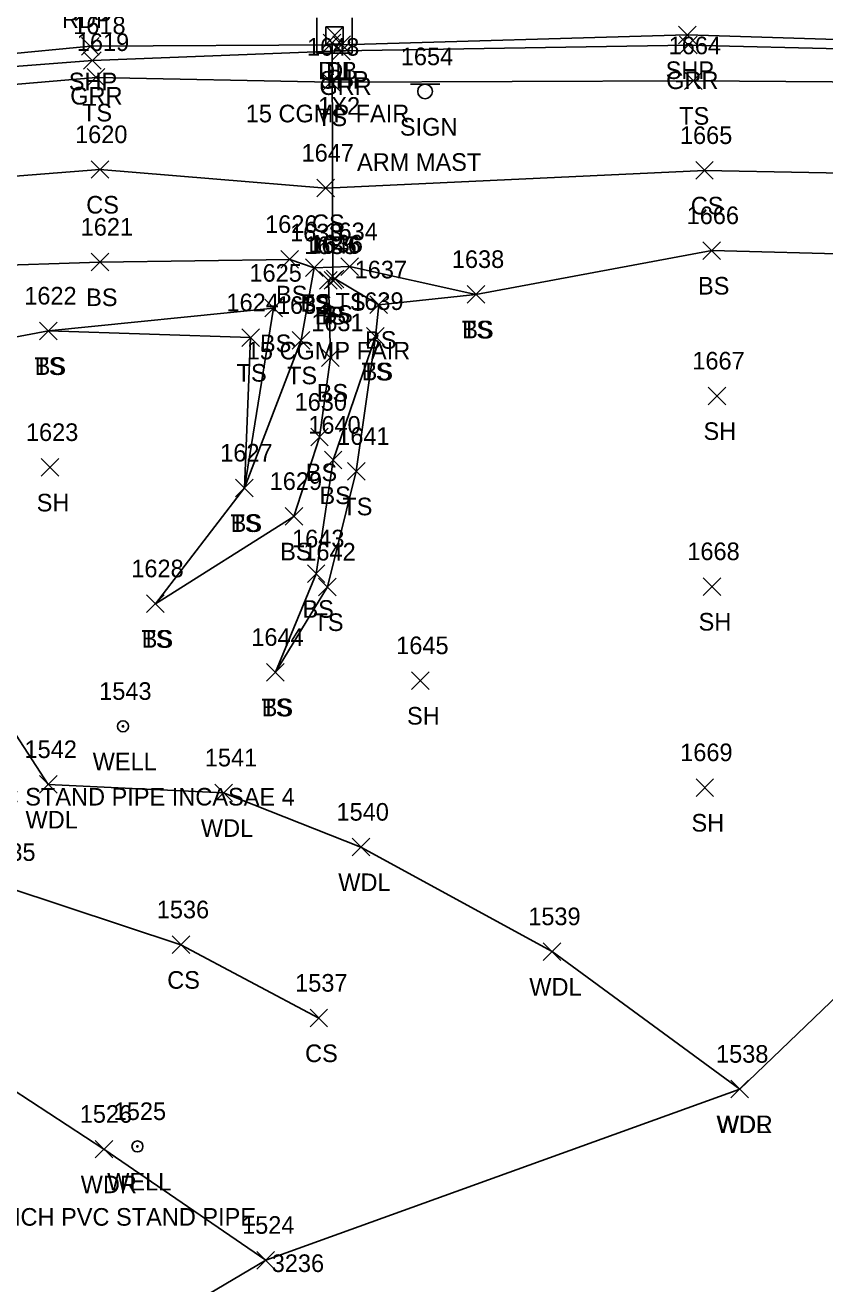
# Model space of a CAD drawing. Extents: x 49137 to 50946, y 9590 to 10709.
# Drawn here: x 50238.1 to 50328.9, y 9912 to 10054.9 of the extents above; entities that cross this region are included whole.
import ezdxf

# ---------------------------------------------------------------- set-up
doc = ezdxf.new("R2010")
doc.units = 0
for name, color, linetype in [('D_A', 7, 'Continuous'), ('D_C', 7, 'Continuous'), ('D_I', 7, 'Continuous'), ('D_TIC', 7, 'Continuous'), ('DCP', 7, 'Continuous'), ('DS', 7, 'Continuous'), ('L_A', 7, 'Continuous'), ('L_I', 7, 'Continuous'), ('L_TIC', 7, 'Continuous'), ('LAWA', 7, 'Continuous'), ('LELB', 7, 'Continuous'), ('LSOGP', 7, 'Continuous'), ('P_A', 7, 'Continuous'), ('P_TIC', 7, 'Continuous'), ('PSP', 7, 'Continuous'), ('R_A', 7, 'Continuous'), ('R_I', 7, 'Continuous'), ('R_TIC', 7, 'Continuous'), ('RGR', 7, 'Continuous'), ('S_A', 7, 'Continuous'), ('S_C', 7, 'Continuous'), ('S_I', 7, 'Continuous'), ('SSGN', 7, 'Continuous'), ('U_A', 7, 'Continuous'), ('U_C', 7, 'Continuous'), ('U_I', 7, 'Continuous'), ('UWW', 7, 'Continuous')]:
    doc.layers.add(name, color=color, linetype=linetype)

msp = doc.modelspace()

# ---------------------------------------------------------------- linework, layer by layer
at = {"layer": 'D_TIC'}
for points in [[(50271.92, 10051.89), (50273.92, 10053.89)], [(50273.92, 10051.89), (50271.92, 10053.89)], [(50272.23, 10052.76), (50274.23, 10054.76)], [(50274.23, 10052.76), (50272.23, 10054.76)], [(50272.02, 10024.96), (50274.02, 10026.96)], [(50274.02, 10024.96), (50272.02, 10026.96)]]:
    msp.add_lwpolyline(points, dxfattribs=at)
at = {"layer": 'DCP'}
msp.add_lwpolyline([(50273.02, 10025.96), (50272.92, 10052.89)], dxfattribs=at)
at = {"layer": 'DS'}
for p, q in [((50271.19, 10051.75), (50271.19, 10055.75)), ((50275.19, 10055.75), (50275.19, 10051.75)), ((50272.19, 10052.75), (50272.19, 10054.75)), ((50272.19, 10054.75), (50274.19, 10054.75)), ((50273.2, 10053.75), (50273.2, 10053.75)), ((50273.2, 10053.75), (50273.2, 10053.75)), ((50274.19, 10054.75), (50274.19, 10052.75)), ((50274.19, 10052.75), (50272.19, 10052.75)), ((50275.19, 10051.75), (50271.19, 10051.75))]:
    msp.add_line(p, q, dxfattribs=at)
at = {"layer": 'L_TIC'}
for points in [[(50245.1, 10047.99), (50247.1, 10049.99)], [(50247.1, 10047.99), (50245.1, 10049.99)], [(50271.8, 10047.46), (50273.8, 10049.46)], [(50273.8, 10047.46), (50271.8, 10049.46)], [(50312.94, 10047.62), (50314.94, 10049.62)], [(50314.94, 10047.62), (50312.94, 10049.62)], [(50245.55, 10037.53), (50247.55, 10039.53)], [(50247.55, 10037.53), (50245.55, 10039.53)], [(50314.22, 10037.43), (50316.22, 10039.43)], [(50316.22, 10037.43), (50314.22, 10039.43)], [(50271.19, 10035.43), (50273.19, 10037.43)], [(50273.19, 10035.43), (50271.19, 10037.43)], [(50267.1, 10027.33), (50269.1, 10029.33)], [(50269.1, 10027.33), (50267.1, 10029.33)], [(50315.04, 10028.33), (50317.04, 10030.33)], [(50317.04, 10028.33), (50315.04, 10030.33)], [(50245.54, 10027.02), (50247.54, 10029.02)], [(50247.54, 10027.02), (50245.54, 10029.02)], [(50269.89, 10026.37), (50271.89, 10028.37)], [(50271.89, 10026.37), (50269.89, 10028.37)], [(50269.89, 10026.37), (50271.89, 10028.37)], [(50271.89, 10026.37), (50269.89, 10028.37)], [(50273.9, 10026.5), (50275.9, 10028.5)], [(50275.9, 10026.5), (50273.9, 10028.5)], [(50271.5, 10024.93), (50273.5, 10026.93)], [(50273.5, 10024.93), (50271.5, 10026.93)], [(50272.27, 10025.11), (50274.27, 10027.11)], [(50274.27, 10025.11), (50272.27, 10027.11)], [(50288.26, 10023.35), (50290.26, 10025.35)], [(50290.26, 10023.35), (50288.26, 10025.35)], [(50288.26, 10023.35), (50290.26, 10025.35)], [(50290.26, 10023.35), (50288.26, 10025.35)], [(50265.27, 10021.79), (50267.27, 10023.79)], [(50267.27, 10021.79), (50265.27, 10023.79)], [(50277.22, 10022.17), (50279.22, 10024.17)], [(50279.22, 10022.17), (50277.22, 10024.17)], [(50277.22, 10022.17), (50279.22, 10024.17)], [(50279.22, 10022.17), (50277.22, 10024.17)], [(50239.69, 10019.2), (50241.69, 10021.2)], [(50241.69, 10019.2), (50239.69, 10021.2)], [(50239.69, 10019.2), (50241.69, 10021.2)], [(50241.69, 10019.2), (50239.69, 10021.2)], [(50276.83, 10018.58), (50278.83, 10020.58)], [(50278.83, 10018.58), (50276.83, 10020.58)], [(50276.83, 10018.58), (50278.83, 10020.58)], [(50278.83, 10018.58), (50276.83, 10020.58)], [(50262.66, 10018.44), (50264.66, 10020.44)], [(50264.66, 10018.44), (50262.66, 10020.44)], [(50268.39, 10018.14), (50270.39, 10020.14)], [(50270.39, 10018.14), (50268.39, 10020.14)], [(50271.73, 10016.17), (50273.73, 10018.17)], [(50273.73, 10016.17), (50271.73, 10018.17)], [(50315.63, 10011.82), (50317.63, 10013.82)], [(50317.63, 10011.82), (50315.63, 10013.82)], [(50270.49, 10007.14), (50272.49, 10009.14)], [(50272.49, 10007.14), (50270.49, 10009.14)], [(50272.04, 10004.53), (50274.04, 10006.53)], [(50274.04, 10004.53), (50272.04, 10006.53)], [(50239.88, 10003.7), (50241.88, 10005.7)], [(50241.88, 10003.7), (50239.88, 10005.7)], [(50274.67, 10003.26), (50276.67, 10005.26)], [(50276.67, 10003.26), (50274.67, 10005.26)], [(50261.95, 10001.37), (50263.95, 10003.37)], [(50263.95, 10001.37), (50261.95, 10003.37)], [(50261.95, 10001.37), (50263.95, 10003.37)], [(50263.95, 10001.37), (50261.95, 10003.37)], [(50261.95, 10001.37), (50263.95, 10003.37)], [(50263.95, 10001.37), (50261.95, 10003.37)], [(50267.58, 9998.14), (50269.58, 10000.14)], [(50269.58, 9998.14), (50267.58, 10000.14)], [(50270.11, 9991.62), (50272.11, 9993.62)], [(50272.11, 9991.62), (50270.11, 9993.62)], [(50271.39, 9990.12), (50273.39, 9992.12)], [(50273.39, 9990.12), (50271.39, 9992.12)], [(50315.06, 9990.17), (50317.06, 9992.17)], [(50317.06, 9990.17), (50315.06, 9992.17)], [(50251.85, 9988.22), (50253.85, 9990.22)], [(50253.85, 9988.22), (50251.85, 9990.22)], [(50251.85, 9988.22), (50253.85, 9990.22)], [(50253.85, 9988.22), (50251.85, 9990.22)], [(50265.48, 9980.43), (50267.48, 9982.43)], [(50267.48, 9980.43), (50265.48, 9982.43)], [(50265.48, 9980.43), (50267.48, 9982.43)], [(50267.48, 9980.43), (50265.48, 9982.43)], [(50281.94, 9979.49), (50283.94, 9981.49)], [(50283.94, 9979.49), (50281.94, 9981.49)], [(50239.67, 9967.69), (50241.67, 9969.69)], [(50241.67, 9967.69), (50239.67, 9969.69)], [(50314.26, 9967.34), (50316.26, 9969.34)], [(50316.26, 9967.34), (50314.26, 9969.34)], [(50259.59, 9966.74), (50261.59, 9968.74)], [(50261.59, 9966.74), (50259.59, 9968.74)], [(50275.2, 9960.58), (50277.2, 9962.58)], [(50277.2, 9960.58), (50275.2, 9962.58)], [(50254.74, 9949.49), (50256.74, 9951.49)], [(50256.74, 9949.49), (50254.74, 9951.49)], [(50296.9, 9948.71), (50298.9, 9950.71)], [(50298.9, 9948.71), (50296.9, 9950.71)], [(50270.41, 9941.16), (50272.41, 9943.16)], [(50272.41, 9941.16), (50270.41, 9943.16)], [(50318.22, 9933.09), (50320.22, 9935.09)], [(50320.22, 9933.09), (50318.22, 9935.09)], [(50318.22, 9933.09), (50320.22, 9935.09)], [(50320.22, 9933.09), (50318.22, 9935.09)], [(50246, 9926.27), (50248, 9928.27)], [(50248, 9926.27), (50246, 9928.27)], [(50264.38, 9913.66), (50266.38, 9915.66)], [(50266.38, 9913.66), (50264.38, 9915.66)]]:
    msp.add_lwpolyline(points, dxfattribs=at)
at = {"layer": 'LAWA'}
for points in [[(50319.22, 9934.09), (50349.18, 9962.81), (50389.74, 9989.92), (50402.83, 10005.7), (50406.6, 10004.03), (50394.1, 9989.59), (50381.28, 9975.89)], [(50265.38, 9914.66), (50247, 9927.27), (50228.2, 9939.52), (50207.29, 9957.54), (50200.22, 9967.59), (50173.05, 9985.49), (50184.13, 9993.14), (50189.69, 9999.35)], [(50319.22, 9934.09), (50297.9, 9949.71), (50276.2, 9961.58), (50260.59, 9967.74), (50240.67, 9968.69), (50230.47, 9984.33), (50224.27, 9984.27), (50203.79, 9997.29), (50189.69, 9999.35)]]:
    msp.add_lwpolyline(points, dxfattribs=at)
at = {"layer": 'LELB'}
for points in [[(50167.44, 10041.81), (50201.55, 10044.88), (50212.32, 10046.12), (50246.1, 10048.99), (50272.8, 10048.46), (50313.94, 10048.62), (50350.81, 10048.34), (50387.74, 10046.03), (50413.04, 10045.35), (50435.45, 10042.61), (50477, 10035.72), (50497.96, 10034.79)], [(50107.47, 10020.38), (50144.2, 10028.78), (50165.65, 10031.22), (50202.05, 10039.61), (50215.24, 10036.08), (50246.55, 10038.53), (50272.19, 10036.43), (50315.22, 10038.43), (50350.77, 10037.74), (50388.31, 10038.81), (50412.12, 10038.05), (50434.22, 10033.95), (50476.27, 10030.6), (50502.33, 10026.06), (50519.95, 10026.12), (50528.33, 10023.44), (50558.5, 10017.09), (50596.1, 10007.75), (50623.13, 10001.96)], [(50278.22, 10023.17), (50289.26, 10024.35), (50316.04, 10029.33), (50350.22, 10028.42), (50386.55, 10029.79), (50399.58, 10030.09)], [(50218.69, 10027.11), (50246.54, 10028.02), (50268.1, 10028.33), (50270.89, 10027.37)], [(50240.69, 10020.2), (50263.66, 10019.44), (50262.95, 10002.37), (50269.39, 10019.14), (50270.89, 10027.37), (50274.9, 10027.5), (50289.26, 10024.35)], [(50252.85, 9989.22), (50268.58, 9999.14), (50271.49, 10008.14), (50272.73, 10017.17), (50272.5, 10025.93), (50273.27, 10026.11), (50278.22, 10023.17), (50277.83, 10019.58), (50273.04, 10005.53), (50271.11, 9992.62), (50266.48, 9981.43)], [(50221.39, 10016.59), (50240.69, 10020.2), (50266.27, 10022.79), (50262.95, 10002.37)], [(50277.83, 10019.58), (50275.67, 10004.26), (50272.39, 9991.12), (50266.48, 9981.43)], [(50262.95, 10002.37), (50252.85, 9989.22)], [(50200.22, 9967.59), (50202.79, 9981.16), (50217.66, 9971.94), (50235.97, 9957.01), (50255.74, 9950.49), (50271.41, 9942.16)]]:
    msp.add_lwpolyline(points, dxfattribs=at)
at = {"layer": 'LSOGP'}
msp.add_lwpolyline([(50172.36, 9837.78), (50185.48, 9838.52), (50189.39, 9851.5), (50202.19, 9864.77), (50219.85, 9877.61), (50226.92, 9887.06), (50233.45, 9889.4), (50242.1, 9900.88), (50265.38, 9914.66), (50319.22, 9934.09), (50349.18, 9962.81), (50381.27, 9975.89), (50394.04, 9971.93), (50398.71, 9968.32), (50400.43, 9966.52), (50406.78, 9963.51), (50419.71, 9962.53), (50427.02, 9958.62), (50466.07, 9973.83), (50480.4, 9980.25), (50492.08, 9978.32), (50501.38, 9976.22)], dxfattribs=at)
at = {"layer": 'P_TIC'}
for points in [[(50244.47, 10051.53), (50246.47, 10053.53)], [(50246.47, 10051.53), (50244.47, 10053.53)], [(50272.99, 10051.71), (50274.99, 10053.71)], [(50274.99, 10051.71), (50272.99, 10053.71)], [(50312.27, 10052.81), (50314.27, 10054.81)], [(50314.27, 10052.81), (50312.27, 10054.81)]]:
    msp.add_lwpolyline(points, dxfattribs=at)
at = {"layer": 'PSP'}
msp.add_lwpolyline([(49745.77, 9936.94), (49791.02, 9949.79), (49838.6, 9962.98), (49884.65, 9976.31), (49920.32, 9986.67), (49952.97, 9996.21), (49993.49, 10007.72), (50041.55, 10020.44), (50079.02, 10029.05), (50103.84, 10034.11), (50138.34, 10040.53), (50167.13, 10044.8), (50204.38, 10048.62), (50245.47, 10052.53), (50273.99, 10052.71), (50313.27, 10053.81), (50350.86, 10052.67), (50388.17, 10050.83), (50414.17, 10048.89), (50435.24, 10046.38), (50477.89, 10041.39), (50498.49, 10037.53)], dxfattribs=at)
at = {"layer": 'R_TIC'}
for points in [[(50312.38, 10051.67), (50314.38, 10053.67)], [(50314.38, 10051.67), (50312.38, 10053.67)], [(50272.98, 10051), (50274.98, 10053)], [(50274.98, 10051), (50272.98, 10053)], [(50244.69, 10049.91), (50246.69, 10051.91)], [(50246.69, 10049.91), (50244.69, 10051.91)]]:
    msp.add_lwpolyline(points, dxfattribs=at)
at = {"layer": 'RGR'}
msp.add_lwpolyline([(49745.96, 9935.74), (49791.34, 9948.66), (49838.49, 9962.28), (49885.39, 9975.73), (49920.7, 9985.37), (49953.18, 9995.29), (49993.74, 10006.79), (50040.75, 10019.43), (50079.3, 10027.88), (50102.09, 10032.68), (50138.52, 10039.64), (50167.15, 10043.61), (50204.31, 10047.75), (50245.69, 10050.91), (50273.98, 10052), (50313.38, 10052.67), (50351, 10051.76), (50388.09, 10049.85), (50414.02, 10047.85), (50436.27, 10045.35), (50477.66, 10040.11), (50498.48, 10036.57)], dxfattribs=at)
at = {"layer": 'SSGN'}
for p, q in [((50281.83, 10048.24), (50285.17, 10048.24)), ((50283.48, 10047.4), (50283.48, 10047.4))]:
    msp.add_line(p, q, dxfattribs=at)
msp.add_circle((50283.48, 10047.4), 0.833, dxfattribs=at)
at = {"layer": 'UWW'}
for centre, radius in [((50249.16, 9975.3), 0.625), ((50249.16, 9975.3), 0.0833), ((50250.81, 9927.58), 0.625), ((50250.81, 9927.58), 0.0833)]:
    msp.add_circle(centre, radius, dxfattribs=at)

# ---------------------------------------------------------------- texts
at = {"layer": 'D_A'}
for s, p in [('DIB', (50271.33, 10048.76)), ('DI', (50272.25, 10048.75)), ('P', (50272.29, 10047.89)), ('P', (50272.4, 10020.96))]:
    msp.add_text(s, height=2, dxfattribs=at).set_placement(p)
at = {"layer": 'D_C'}
for s, p in [('1X2', (50271.34, 10044.75)), ('15 CGMP FAIR', (50263.11, 10043.89)), ('15 CGMP FAIR', (50263.22, 10016.96))]:
    msp.add_text(s, height=2, dxfattribs=at).set_placement(p)
at = {"layer": 'D_I'}
msp.add_text('1646', height=2, dxfattribs=at).set_placement((50270.23, 10028.96))
at = {"layer": 'L_A'}
for s, p in [('TS', (50244.51, 10043.99)), ('TS', (50271.21, 10043.46)), ('TS', (50312.35, 10043.62)), ('CS', (50244.99, 10033.53)), ('CS', (50313.66, 10033.43)), ('CS', (50270.63, 10031.43)), ('BS', (50314.48, 10024.33)), ('BS', (50244.98, 10023.02)), ('BS', (50266.54, 10023.33)), ('TS', (50269.3, 10022.37)), ('BS', (50269.33, 10022.37)), ('TS', (50273.31, 10022.5)), ('BS', (50270.94, 10020.93)), ('BS', (50271.71, 10021.11)), ('TS', (50287.67, 10019.35)), ('BS', (50287.7, 10019.35)), ('BS', (50264.72, 10017.79)), ('BS', (50276.66, 10018.17)), ('BS', (50276.66, 10018.17)), ('TS', (50239.1, 10015.2)), ('BS', (50239.13, 10015.2)), ('TS', (50262.07, 10014.44)), ('TS', (50276.24, 10014.58)), ('BS', (50276.27, 10014.58)), ('TS', (50267.8, 10014.14)), ('BS', (50271.17, 10012.17)), ('SH', (50315.11, 10007.82)), ('BS', (50269.93, 10003.14)), ('BS', (50271.48, 10000.53)), ('SH', (50239.36, 9999.7)), ('TS', (50274.08, 9999.26)), ('TS', (50261.36, 9997.37)), ('TS', (50261.36, 9997.37)), ('BS', (50261.39, 9997.37)), ('BS', (50267.02, 9994.14)), ('BS', (50269.55, 9987.62)), ('TS', (50270.8, 9986.12)), ('SH', (50314.55, 9986.17)), ('TS', (50251.26, 9984.22)), ('BS', (50251.29, 9984.22)), ('TS', (50264.88, 9976.43)), ('BS', (50264.92, 9976.43)), ('SH', (50281.43, 9975.49)), ('WDL', (50238.09, 9963.69)), ('SH', (50313.74, 9963.34)), ('WDL', (50258.01, 9962.74)), ('WDL', (50273.62, 9956.58)), ('CS', (50254.19, 9945.49)), ('WDL', (50295.32, 9944.71)), ('CS', (50269.85, 9937.16)), ('WDR', (50316.58, 9929.09)), ('WDL', (50316.64, 9929.09)), ('WDR', (50244.36, 9922.27))]:
    msp.add_text(s, height=2, dxfattribs=at).set_placement(p)
at = {"layer": 'L_I'}
for s, p in [('1619', (50243.92, 10051.99)), ('1648', (50270.06, 10051.46)), ('1664', (50311.15, 10051.62)), ('1620', (50243.72, 10041.53)), ('1665', (50312.43, 10041.43)), ('1647', (50269.45, 10039.43)), ('1666', (50313.19, 10032.33)), ('1621', (50244.36, 10031.02)), ('1626', (50265.31, 10031.33)), ('1633', (50268.15, 10030.37)), ('1633', (50268.15, 10030.37)), ('1634', (50272.16, 10030.5)), ('1635', (50269.76, 10028.93)), ('1636', (50270.47, 10029.11)), ('1638', (50286.52, 10027.35)), ('1638', (50286.52, 10027.35)), ('1625', (50263.53, 10025.79)), ('1637', (50275.48, 10026.17)), ('1637', (50275.48, 10026.17)), ('1622', (50237.95, 10023.2)), ('1622', (50237.95, 10023.2)), ('1624', (50260.92, 10022.44)), ('1632', (50266.65, 10022.14)), ('1639', (50275.09, 10022.58)), ('1639', (50275.09, 10022.58)), ('1631', (50270.55, 10020.17)), ('1667', (50313.84, 10015.82)), ('1630', (50268.66, 10011.14)), ('1623', (50238.14, 10007.7)), ('1640', (50270.21, 10008.53)), ('1641', (50273.5, 10007.26)), ('1627', (50260.21, 10005.37)), ('1627', (50260.21, 10005.37)), ('1627', (50260.21, 10005.37)), ('1629', (50265.83, 10002.14)), ('1643', (50268.37, 9995.62)), ('1642', (50269.65, 9994.12)), ('1668', (50313.27, 9994.17)), ('1628', (50250.11, 9992.22)), ('1628', (50250.11, 9992.22)), ('1644', (50263.74, 9984.43)), ('1644', (50263.74, 9984.43)), ('1645', (50280.2, 9983.49)), ('1542', (50237.98, 9971.69)), ('1541', (50258.46, 9970.74)), ('1669', (50312.46, 9971.34)), ('1540', (50273.42, 9964.58)), ('1535', (50233.28, 9960.01)), ('1536', (50253, 9953.49)), ('1539', (50295.2, 9952.71)), ('1537', (50268.72, 9945.16)), ('1538', (50316.53, 9937.09)), ('1538', (50316.53, 9937.09)), ('1526', (50244.25, 9930.27)), ('1524', (50262.69, 9917.66)), ('3236', (50266.06, 9913.32))]:
    msp.add_text(s, height=2, dxfattribs=at).set_placement(p)
at = {"layer": 'P_A'}
for s, p in [('RDP', (50242.23, 10054.59)), ('SHP', (50310.81, 10048.81)), ('SHP', (50243.01, 10047.53)), ('SHP', (50271.53, 10047.71))]:
    msp.add_text(s, height=2, dxfattribs=at).set_placement(p)
at = {"layer": 'R_A'}
for p in [(50310.87, 10047.67), (50243.17, 10045.91), (50271.47, 10047)]:
    msp.add_text('GRR', height=2, dxfattribs=at).set_placement(p)
at = {"layer": 'R_I'}
msp.add_text('1618', height=2, dxfattribs=at).set_placement((50243.51, 10053.91))
at = {"layer": 'S_A'}
msp.add_text('SIGN', height=2, dxfattribs=at).set_placement((50280.62, 10042.38))
at = {"layer": 'S_C'}
msp.add_text('ARM MAST', height=2, dxfattribs=at).set_placement((50275.75, 10038.38))
at = {"layer": 'S_I'}
msp.add_text('1654', height=2, dxfattribs=at).set_placement((50280.72, 10050.38))
at = {"layer": 'U_A'}
for p in [(50245.72, 9970.3), (50247.37, 9922.58)]:
    msp.add_text('WELL', height=2, dxfattribs=at).set_placement(p)
at = {"layer": 'U_C'}
for s, p in [('2 INCH PVC STAND PIPE INCASAE 4', (50222.31, 9966.3)), ('2 INCH PVC STAND PIPE', (50232.62, 9918.58))]:
    msp.add_text(s, height=2, dxfattribs=at).set_placement(p)
at = {"layer": 'U_I'}
for s, p in [('1543', (50246.46, 9978.3)), ('1525', (50248.11, 9930.58))]:
    msp.add_text(s, height=2, dxfattribs=at).set_placement(p)

doc.saveas('drawing.dxf')
